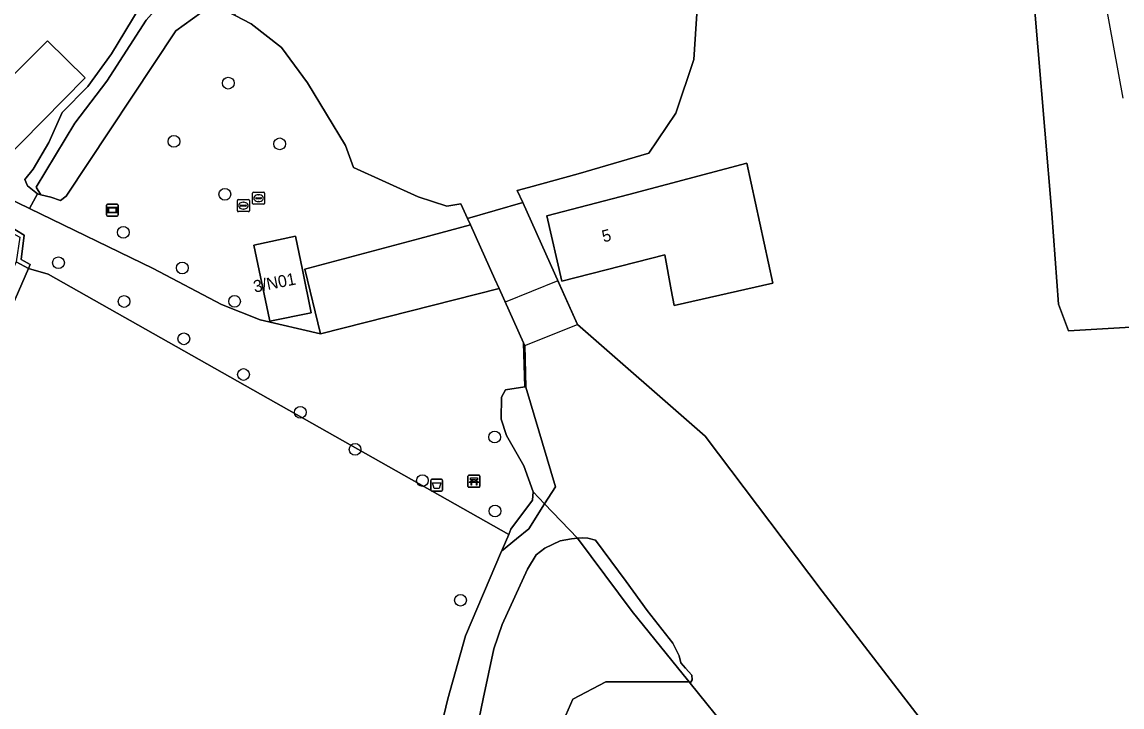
# Model space of a CAD drawing. Extents: x 164494 to 166241, y 382475 to 384495.
# Drawn here: x 165431.6 to 165523.2, y 383999.3 to 384056.4 of the extents above; entities that cross this region are included whole.
import ezdxf

# ---------------------------------------------------------------- set-up
doc = ezdxf.new("R2010")
doc.units = 0
for name, color, linetype in [('IMGEO_Afvalbak', 7, 'Continuous'), ('IMGEO_Bank', 7, 'Continuous'), ('IMGEO_Boom', 7, 'Continuous'), ('IMGEO_Erf', 7, 'Continuous'), ('IMGEO_Grasland_agrarisch', 7, 'Continuous'), ('IMGEO_Groenvoorziening', 7, 'Continuous'), ('IMGEO_Informatiebord', 7, 'Continuous'), ('IMGEO_Kademuur', 7, 'Continuous'), ('IMGEO_Loofbos', 7, 'Continuous'), ('IMGEO_Meer_plas_ven_vijver', 7, 'Continuous'), ('IMGEO_Muur', 7, 'Continuous'), ('IMGEO_Oever', 7, 'Continuous'), ('IMGEO_Pand', 7, 'Continuous'), ('IMGEO_Pand_nummerreeks', 7, 'Continuous'), ('IMGEO_Rioolput', 7, 'Continuous'), ('IMGEO_Rivier', 7, 'Continuous'), ('IMGEO_Stuw', 7, 'Continuous'), ('IMGEO_Voetpad_halfverhard', 7, 'Continuous'), ('IMGEO_Voetpad_open', 7, 'Continuous'), ('IMGEO_Waterloop', 7, 'Continuous')]:
    doc.layers.add(name, color=color, linetype=linetype)

msp = doc.modelspace()

# ---------------------------------------------------------------- linework, layer by layer
at = {"layer": 'IMGEO_Afvalbak'}
for p, q in [((165465.615, 384017.388), (165465.615, 384018.188)), ((165465.615, 384018.188), (165465.615, 384017.388)), ((165465.715, 384018.288), (165466.505, 384018.288)), ((165466.505, 384018.288), (165465.715, 384018.288)), ((165466.605, 384018.188), (165466.605, 384017.388)), ((165466.605, 384017.388), (165466.605, 384018.188)), ((165466.505, 384017.288), (165465.715, 384017.288)), ((165465.715, 384017.288), (165466.505, 384017.288))]:
    msp.add_line(p, q, dxfattribs=at)
msp.add_lwpolyline([(165465.758, 384018.002), (165466.462, 384018.002), (165466.313, 384017.532), (165465.907, 384017.532), (165465.758, 384018.002)], dxfattribs=at)
for centre, start, end in [((165465.715, 384018.188), 90, 180), ((165465.715, 384018.188), 90, 180), ((165466.505, 384018.188), 0, 90), ((165466.505, 384018.188), 360, 90), ((165465.715, 384017.388), 180, 270), ((165465.715, 384017.388), 180, 270), ((165466.505, 384017.388), 270, 0), ((165466.505, 384017.388), 270, 0)]:
    msp.add_arc(centre, 0.1, start, end, dxfattribs=at)
at = {"layer": 'IMGEO_Bank'}
for p, q in [((165468.791, 384018.62), (165469.632, 384018.62)), ((165469.632, 384018.62), (165468.791, 384018.62)), ((165468.716, 384017.695), (165468.716, 384018.536)), ((165468.716, 384018.536), (165468.716, 384017.695)), ((165469.413, 384018.018), (165469.02, 384018.018)), ((165469.025, 384018.126), (165469.025, 384018.232)), ((165469.069, 384018.232), (165469.069, 384018.126)), ((165469.357, 384018.238), (165469.075, 384018.238)), ((165469.075, 384018.12), (165469.357, 384018.12)), ((165469.363, 384018.126), (165469.363, 384018.232)), ((165469.407, 384018.232), (165469.407, 384018.126)), ((165469.716, 384018.545), (165469.716, 384017.704)), ((165469.716, 384017.704), (165469.716, 384018.545)), ((165469.641, 384017.62), (165468.8, 384017.62)), ((165468.8, 384017.62), (165469.641, 384017.62))]:
    msp.add_line(p, q, dxfattribs=at)
for points in [[(165468.963, 384018.018), (165468.821, 384018.018), (165468.933, 384018.12), (165469.019, 384018.12)], [(165469.019, 384018.238), (165468.933, 384018.238), (165468.933, 384018.399), (165469.496, 384018.399), (165469.496, 384018.238), (165469.413, 384018.238)], [(165469.013, 384018.011), (165469.013, 384017.804), (165468.97, 384017.804), (165468.97, 384018.011)], [(165469.413, 384018.12), (165469.496, 384018.12), (165469.608, 384018.018), (165469.469, 384018.018)], [(165469.463, 384018.011), (165469.463, 384017.804), (165469.419, 384017.804), (165469.419, 384018.011)]]:
    msp.add_lwpolyline(points, dxfattribs=at)
for centre, radius, start, end in [((165468.794, 384018.542), 0.0779, 92.4484, 184.28452), ((165468.794, 384018.542), 0.0779, 92.4484, 184.28452), ((165469.638, 384018.542), 0.0779, 2.4484, 94.28452), ((165469.638, 384018.542), 0.0779, 2.4484, 94.28452), ((165468.794, 384017.698), 0.0779, 182.4484, 274.28452), ((165468.794, 384017.698), 0.0779, 182.4484, 274.28452), ((165468.963, 384018.011), 0.00671, 2.89567, 87.10433), ((165469.02, 384018.011), 0.00671, 92.89567, 177.10433), ((165469.018, 384018.231), 0.00671, 2.89567, 87.10433), ((165469.018, 384018.127), 0.00671, 272.89567, 357.10433), ((165469.075, 384018.231), 0.00671, 92.89567, 177.10433), ((165469.075, 384018.127), 0.00671, 182.89567, 267.10433), ((165469.357, 384018.231), 0.00671, 2.89567, 87.10433), ((165469.357, 384018.127), 0.00671, 272.89567, 357.10433), ((165469.414, 384018.231), 0.00671, 92.89567, 177.10433), ((165469.414, 384018.127), 0.00671, 182.89567, 267.10433), ((165469.412, 384018.011), 0.00671, 2.89567, 87.10433), ((165469.469, 384018.011), 0.00671, 92.89567, 177.10433), ((165469.638, 384017.698), 0.0779, 272.4484, 4.28452), ((165469.638, 384017.698), 0.0779, 272.4484, 4.28452)]:
    msp.add_arc(centre, radius, start, end, dxfattribs=at)
at = {"layer": 'IMGEO_Boom'}
for centre in [(165448.763, 384051.265), (165444.24, 384046.415), (165453.041, 384046.211), (165448.478, 384042.013), (165440.024, 384038.844), (165434.628, 384036.311), (165444.934, 384035.881), (165440.092, 384033.088), (165449.286, 384033.097), (165445.064, 384029.981), (165450.03, 384027.01), (165454.759, 384023.863), (165470.94, 384021.8), (165459.322, 384020.773), (165464.924, 384018.179), (165470.969, 384015.645), (165468.095, 384008.218)]:
    msp.add_circle(centre, 0.489, dxfattribs=at)
at = {"layer": 'IMGEO_Erf'}
msp.add_lwpolyline([(165409.157, 384052.399), (165413.571, 384049.73), (165419.448, 384047.004), (165432.21, 384040.827), (165432.889, 384042.04), (165432.059, 384042.703), (165431.835, 384043.241), (165432.508, 384044.106), (165433.832, 384046.315), (165434.934, 384048.823), (165437.077, 384050.998), (165439.037, 384053.712), (165441.349, 384057.507)], dxfattribs=at)
msp.add_lwpolyline([(165425.935, 384046.612), (165426.859, 384047.528), (165426.648, 384047.742), (165433.701, 384054.796), (165436.839, 384051.712), (165429.803, 384044.559), (165429.591, 384044.772), (165428.667, 384043.856)], close=True, dxfattribs=at)
at = {"layer": 'IMGEO_Grasland_agrarisch'}
msp.add_lwpolyline([(165465.876, 383995.163), (165467.034, 384000), (165468.503, 384005.261), (165471.517, 384012.308), (165471.562, 384012.413), (165472.114, 384013.698), (165433.758, 384035.364), (165432.127, 384035.844), (165425.699, 384021.103), (165420.906, 384009.219), (165420.603, 384008.641), (165397.653, 383961.837), (165387.56, 383941.909), (165384.176, 383935.455), (165366.719, 383898.707), (165373.354, 383895.442), (165395.688, 383886.318), (165424.197, 383875.062), (165430.956, 383872.05), (165432.029, 383878.537), (165432.519, 383879.96)], close=True, dxfattribs=at)
at = {"layer": 'IMGEO_Groenvoorziening'}
msp.add_lwpolyline([(165446.488, 384057.105), (165444.409, 384055.62), (165435.262, 384041.866), (165434.805, 384041.502), (165433.992, 384041.779), (165433.161, 384041.976), (165432.889, 384042.04), (165432.21, 384040.827), (165442.521, 384035.836), (165448.2, 384032.837), (165451.407, 384031.56), (165456.428, 384030.39), (165455.125, 384035.773), (165461.805, 384037.565), (165464.707, 384038.343), (165468.922, 384039.474), (165468.684, 384040.002), (165468.134, 384041.224), (165466.955, 384041.026), (165464.566, 384041.808), (165459.18, 384044.242), (165458.528, 384046.067), (165455.357, 384051.282), (165453.185, 384054.237), (165450.666, 384056.192), (165449.323, 384056.885)], dxfattribs=at)
for points in [[(165452.192, 384031.576), (165450.879, 384037.771), (165454.351, 384038.534), (165454.931, 384035.721), (165455.669, 384032.143), (165452.221, 384031.44)], [(165475.099, 384016.248), (165474.155, 384017.239), (165474.1, 384016.539), (165472.298, 384014.126), (165472.114, 384013.698), (165471.562, 384012.413), (165471.517, 384012.308), (165472.766, 384013.33), (165473.777, 384014.157)]]:
    msp.add_lwpolyline(points, close=True, dxfattribs=at)
at = {"layer": 'IMGEO_Informatiebord'}
for p, q in [((165438.619, 384040.303), (165438.619, 384041.103)), ((165438.619, 384041.103), (165438.619, 384040.303)), ((165438.719, 384041.203), (165439.509, 384041.203)), ((165439.509, 384041.203), (165438.719, 384041.203)), ((165439.609, 384041.103), (165439.609, 384040.303)), ((165439.609, 384040.303), (165439.609, 384041.103)), ((165439.509, 384040.203), (165438.719, 384040.203)), ((165438.719, 384040.203), (165439.509, 384040.203))]:
    msp.add_line(p, q, dxfattribs=at)
for points in [[(165438.72, 384040.935), (165439.508, 384040.935), (165439.508, 384040.471), (165438.72, 384040.471), (165438.72, 384040.935)], [(165438.785, 384040.87), (165438.785, 384040.536), (165439.443, 384040.536), (165439.443, 384040.87), (165438.785, 384040.87)]]:
    msp.add_lwpolyline(points, dxfattribs=at)
for centre, start, end in [((165438.719, 384041.103), 90, 180), ((165438.719, 384041.103), 90, 180), ((165439.509, 384041.103), 0, 90), ((165439.509, 384041.103), 360, 90), ((165438.719, 384040.303), 180, 270), ((165438.719, 384040.303), 180, 270), ((165439.509, 384040.303), 270, 0), ((165439.509, 384040.303), 270, 0)]:
    msp.add_arc(centre, 0.1, start, end, dxfattribs=at)
at = {"layer": 'IMGEO_Kademuur'}
msp.add_lwpolyline([(165473.448, 384029.416), (165473.349, 384029.636), (165473.449, 384025.975), (165473.547, 384025.965)], close=True, dxfattribs=at)
at = {"layer": 'IMGEO_Loofbos'}
for points in [[(165528.619, 384031.237), (165518.715, 384030.641), (165517.882, 384032.878), (165517.326, 384040.425), (165514.398, 384075.127)], [(165488.101, 384062.158), (165487.517, 384053.227), (165486.013, 384048.771), (165483.768, 384045.436), (165477.897, 384043.717), (165473.753, 384042.585), (165472.819, 384042.341), (165473.273, 384041.33), (165477.842, 384031.179), (165488.462, 384021.886), (165498.192, 384008.958), (165514.916, 383987.284)], [(165476.096, 383996.884), (165477.444, 383999.973), (165480.198, 384001.416), (165487.134, 384001.416), (165486.629, 384002.043), (165482.39, 384007.265), (165477.828, 384013.383), (165477.331, 384013.331), (165476.382, 384013.155), (165475.107, 384012.546), (165474.391, 384012.001), (165473.68, 384010.816), (165471.559, 384006.194), (165470.87, 384004.177), (165469.99, 384000), (165468.917, 383994.905)]]:
    msp.add_lwpolyline(points, dxfattribs=at)
msp.add_lwpolyline([(165491.937, 384044.593), (165494.082, 384034.6), (165485.883, 384032.747), (165485.641, 384034.068), (165485.108, 384036.979), (165476.53, 384034.792), (165475.284, 384040.213), (165482.098, 384042.005)], close=True, dxfattribs=at)
at = {"layer": 'IMGEO_Meer_plas_ven_vijver'}
msp.add_lwpolyline([(165490.561, 383997.138), (165487.225, 384001.303), (165487.134, 384001.416), (165480.198, 384001.416), (165477.444, 383999.973), (165476.096, 383996.884)], dxfattribs=at)
at = {"layer": 'IMGEO_Muur'}
msp.add_lwpolyline([(165428.079, 384038.337), (165428.232, 384038.256), (165430.446, 384038.958), (165431.397, 384038.432), (165431.116, 384036.401), (165432.127, 384035.844), (165432.264, 384036.165), (165431.524, 384036.587), (165431.768, 384038.601), (165430.503, 384039.392), (165430.27, 384039.313), (165428.209, 384038.616), (165426.938, 384039.344), (165426.748, 384039.045)], close=True, dxfattribs=at)
at = {"layer": 'IMGEO_Oever'}
msp.add_lwpolyline([(165441.349, 384057.507), (165439.037, 384053.712), (165437.077, 384050.998), (165434.934, 384048.823), (165433.832, 384046.315), (165432.508, 384044.106), (165431.835, 384043.241), (165432.059, 384042.703), (165432.889, 384042.04), (165433.161, 384041.976), (165432.759, 384042.615), (165435.98, 384047.93), (165438.654, 384051.429), (165441.935, 384056.511), (165443.481, 384058.289), (165444.876, 384059.343), (165447.278, 384060.842), (165448.745, 384061.816)], dxfattribs=at)
for points in [[(165425.699, 384021.103), (165432.127, 384035.844), (165431.116, 384036.401), (165419.214, 384010.042), (165418.943, 384009.502), (165420.603, 384008.641), (165420.906, 384009.219)], [(165473.547, 384025.965), (165473.449, 384025.975), (165471.836, 384025.744), (165471.5, 384025.121), (165471.474, 384023.301), (165471.923, 384021.923), (165473.36, 384019.394), (165474.155, 384017.239), (165475.099, 384016.248), (165475.999, 384017.671)], [(165481.892, 384009.783), (165479.32, 384013.226), (165478.69, 384013.389), (165478.221, 384013.424), (165477.828, 384013.383), (165482.39, 384007.265), (165486.629, 384002.043), (165487.134, 384001.416), (165487.225, 384001.303), (165487.378, 384001.58), (165487.343, 384001.978), (165486.828, 384002.564), (165486.43, 384003.009), (165486.289, 384003.594), (165485.78, 384004.642), (165483.637, 384007.37)]]:
    msp.add_lwpolyline(points, close=True, dxfattribs=at)
at = {"layer": 'IMGEO_Pand'}
for points in [[(165425.935, 384046.612), (165428.667, 384043.856), (165429.591, 384044.772), (165429.803, 384044.559), (165436.839, 384051.712), (165433.701, 384054.796), (165426.648, 384047.742), (165426.859, 384047.528)], [(165491.937, 384044.593), (165482.098, 384042.005), (165475.284, 384040.213), (165476.53, 384034.792), (165485.108, 384036.979), (165485.641, 384034.068), (165485.883, 384032.747), (165494.082, 384034.6)], [(165455.125, 384035.773), (165456.428, 384030.39), (165471.304, 384034.18), (165470.96, 384034.945), (165468.922, 384039.474), (165464.707, 384038.343), (165461.805, 384037.565)], [(165454.931, 384035.721), (165454.351, 384038.534), (165450.879, 384037.771), (165452.192, 384031.576), (165452.221, 384031.44), (165455.669, 384032.143)]]:
    msp.add_lwpolyline(points, close=True, dxfattribs=at)
at = {"layer": 'IMGEO_Rioolput'}
for p, q in [((165449.517, 384040.64), (165449.517, 384041.492)), ((165449.592, 384041.566), (165450.444, 384041.566)), ((165450.518, 384041.492), (165450.518, 384040.64)), ((165450.787, 384041.259), (165450.787, 384042.111)), ((165450.862, 384042.185), (165451.714, 384042.185)), ((165451.046, 384041.679), (165451.046, 384041.691)), ((165451.484, 384041.642), (165451.086, 384041.642)), ((165451.089, 384041.728), (165451.487, 384041.728)), ((165451.275, 384041.965), (165451.3, 384041.965)), ((165451.53, 384041.691), (165451.53, 384041.679)), ((165451.788, 384042.111), (165451.788, 384041.259)), ((165450.444, 384040.566), (165449.592, 384040.566)), ((165449.776, 384041.06), (165449.776, 384041.072)), ((165450.214, 384041.023), (165449.816, 384041.023)), ((165449.819, 384041.109), (165450.217, 384041.109)), ((165450.028, 384040.786), (165450.003, 384040.786)), ((165450.005, 384041.346), (165450.03, 384041.346)), ((165450.26, 384041.072), (165450.26, 384041.06)), ((165451.714, 384041.185), (165450.862, 384041.185)), ((165451.298, 384041.405), (165451.273, 384041.405))]:
    msp.add_line(p, q, dxfattribs=at)
for points in [[(165449.517, 384040.64), (165449.517, 384041.492)], [(165449.592, 384041.566), (165450.444, 384041.566)], [(165450.518, 384041.492), (165450.518, 384040.64)], [(165450.787, 384041.259), (165450.787, 384042.111)], [(165450.862, 384042.185), (165451.714, 384042.185)], [(165451.788, 384042.111), (165451.788, 384041.259)], [(165450.444, 384040.566), (165449.592, 384040.566)], [(165451.714, 384041.185), (165450.862, 384041.185)]]:
    msp.add_lwpolyline(points, dxfattribs=at)
for centre, radius, start, end in [((165449.594, 384041.49), 0.0765, 91.55205, 178.44795), ((165449.594, 384041.49), 0.0765, 91.55205, 178.44795), ((165450.442, 384041.49), 0.0765, 1.55205, 88.44795), ((165450.442, 384041.49), 0.0765, 1.55205, 88.44795), ((165450.864, 384042.109), 0.0765, 91.55205, 178.44795), ((165450.864, 384042.109), 0.0765, 91.55205, 178.44795), ((165451.086, 384041.688), 0.0403, 85.87752, 175.75265), ((165451.083, 384041.678), 0.0366, 178.93798, 274.71019), ((165451.487, 384041.685), 0.043, 264.86636, 352.45326), ((165451.491, 384041.69), 0.0386, 1.73085, 96.63898), ((165451.712, 384042.109), 0.0765, 1.55205, 88.44795), ((165451.712, 384042.109), 0.0765, 1.55205, 88.44795), ((165449.594, 384040.642), 0.0765, 181.55205, 268.44795), ((165449.594, 384040.642), 0.0765, 181.55205, 268.44795), ((165449.816, 384041.069), 0.0403, 85.87752, 175.75265), ((165449.813, 384041.059), 0.0366, 178.93798, 274.71019), ((165450.217, 384041.066), 0.043, 264.86636, 352.45326), ((165450.221, 384041.071), 0.0386, 1.73085, 96.63898), ((165450.442, 384040.642), 0.0765, 271.55205, 358.44795), ((165450.442, 384040.642), 0.0765, 271.55205, 358.44795), ((165450.864, 384041.261), 0.0765, 181.55205, 268.44795), ((165450.864, 384041.261), 0.0765, 181.55205, 268.44795), ((165451.712, 384041.261), 0.0765, 271.55205, 358.44795), ((165451.712, 384041.261), 0.0765, 271.55205, 358.44795)]:
    msp.add_arc(centre, radius, start, end, dxfattribs=at)
for centre, major_axis, ratio, start_param, end_param in [((165451.274, 384041.685), (-0.387, 0.002), 0.722429, 4.712389, 7.853982), ((165451.299, 384041.685), (-0.39, 0.002), 0.717154, 1.570796, 4.712389), ((165450.004, 384041.066), (-0.387, 0.002), 0.722429, 4.712389, 7.853982), ((165450.029, 384041.066), (-0.39, 0.002), 0.717154, 1.570796, 4.712389)]:
    msp.add_ellipse(centre, major_axis=major_axis, ratio=ratio, start_param=start_param, end_param=end_param, dxfattribs=at)
at = {"layer": 'IMGEO_Rivier'}
for points in [[(165523.269, 384050.023), (165519.785, 384068.995), (165518.981, 384075.228), (165518.268, 384082.62), (165517.936, 384085.479), (165517.918, 384085.675), (165513.672, 384084.918), (165513.847, 384083.517), (165513.99, 384080.078), (165514.398, 384075.127), (165517.326, 384040.425), (165517.882, 384032.878), (165518.715, 384030.641), (165528.619, 384031.237)], [(165449.323, 384056.885), (165450.666, 384056.192), (165453.185, 384054.237), (165455.357, 384051.282), (165458.528, 384046.067), (165459.18, 384044.242), (165464.566, 384041.808), (165466.955, 384041.026), (165468.134, 384041.224), (165468.684, 384040.002), (165473.273, 384041.33), (165472.819, 384042.341), (165473.753, 384042.585), (165477.897, 384043.717), (165483.768, 384045.436), (165486.013, 384048.771), (165487.517, 384053.227), (165488.101, 384062.158)], [(165514.916, 383987.284), (165498.192, 384008.958), (165488.462, 384021.886), (165477.842, 384031.179), (165473.273, 384041.33), (165468.684, 384040.002), (165468.922, 384039.474), (165470.96, 384034.945), (165471.304, 384034.18), (165473.349, 384029.636), (165473.448, 384029.416), (165473.547, 384025.965), (165475.999, 384017.671), (165475.099, 384016.248), (165477.828, 384013.383), (165478.221, 384013.424), (165478.69, 384013.389), (165479.32, 384013.226), (165481.892, 384009.783), (165483.637, 384007.37), (165485.78, 384004.642), (165486.289, 384003.594), (165486.43, 384003.009), (165486.828, 384002.564), (165487.343, 384001.978), (165487.378, 384001.58), (165487.225, 384001.303), (165490.561, 383997.138)]]:
    msp.add_lwpolyline(points, dxfattribs=at)
at = {"layer": 'IMGEO_Stuw'}
msp.add_lwpolyline([(165468.684, 384040.002), (165473.273, 384041.33)], dxfattribs=at)
at = {"layer": 'IMGEO_Voetpad_halfverhard'}
msp.add_lwpolyline([(165430.503, 384039.392), (165431.768, 384038.601), (165431.524, 384036.587), (165432.264, 384036.165), (165432.127, 384035.844), (165433.758, 384035.364), (165472.114, 384013.698), (165472.298, 384014.126), (165474.1, 384016.539), (165474.155, 384017.239), (165473.36, 384019.394), (165471.923, 384021.923), (165471.474, 384023.301), (165471.5, 384025.121), (165471.836, 384025.744), (165473.449, 384025.975), (165473.349, 384029.636), (165471.304, 384034.18), (165456.428, 384030.39), (165451.407, 384031.56), (165448.2, 384032.837), (165442.521, 384035.836), (165432.21, 384040.827), (165419.448, 384047.004)], dxfattribs=at)
at = {"layer": 'IMGEO_Voetpad_open'}
msp.add_lwpolyline([(165476.211, 384034.802), (165471.818, 384033.039), (165473.349, 384029.636), (165473.448, 384029.416), (165477.842, 384031.179)], close=True, dxfattribs=at)
at = {"layer": 'IMGEO_Waterloop'}
msp.add_lwpolyline([(165444.409, 384055.62), (165446.488, 384057.105), (165447.886, 384057.626), (165449.323, 384056.885), (165448.745, 384061.816), (165447.278, 384060.842), (165444.876, 384059.343), (165443.481, 384058.289), (165441.935, 384056.511), (165438.654, 384051.429), (165435.98, 384047.93), (165432.759, 384042.615), (165433.161, 384041.976), (165433.992, 384041.779), (165434.805, 384041.502), (165435.262, 384041.866)], close=True, dxfattribs=at)
msp.add_lwpolyline([(165468.917, 383994.905), (165469.99, 384000), (165470.87, 384004.177), (165471.559, 384006.194), (165473.68, 384010.816), (165474.391, 384012.001), (165475.107, 384012.546), (165476.382, 384013.155), (165477.331, 384013.331), (165477.828, 384013.383), (165475.099, 384016.248), (165473.777, 384014.157), (165472.766, 384013.33), (165471.517, 384012.308), (165468.503, 384005.261), (165467.034, 384000), (165465.876, 383995.163)], dxfattribs=at)

# ---------------------------------------------------------------- texts
at = {"layer": 'IMGEO_Pand_nummerreeks'}
for s, rotation, p in [('5', 14.30103, (165480.007, 384038)), ('3/N01', 11.10057, (165450.954, 384033.823))]:
    msp.add_text(s, height=1, rotation=rotation, dxfattribs=at).set_placement(p)

doc.saveas('drawing.dxf')
